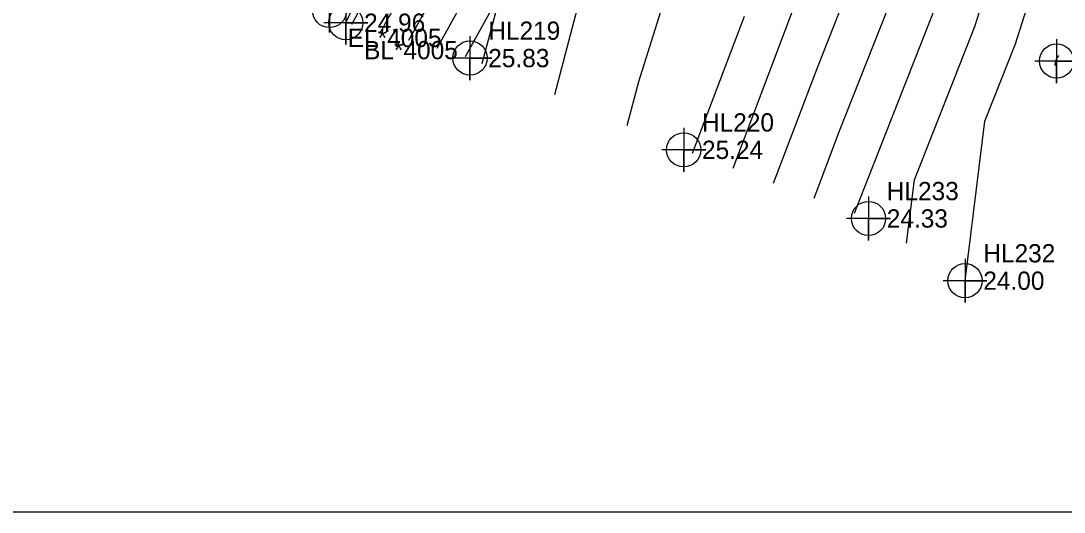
# Model space of a CAD drawing. Extents: x 2531902 to 2533249, y 715219 to 716099.
# Drawn here: x 2532689.5 to 2532832.3, y 715219 to 715286.2 of the extents above; entities that cross this region are included whole.
import ezdxf

# ---------------------------------------------------------------- set-up
doc = ezdxf.new("R2010")
doc.units = 0
for name, color, linetype in [('DTM Contours Major', 7, 'Continuous'), ('DTM Contours Minor', 7, 'Continuous'), ('Exist DTM Breakline', 7, 'Continuous'), ('Exist DTM Breakline Cogo Comment', 7, 'Continuous'), ('Exist DTM Breakline Cogo Elevation', 7, 'Continuous'), ('Exist DTM Breakline Cogo Point CELL', 7, 'Continuous'), ('Exist DTM Regular Point CELL', 7, 'Continuous'), ('Exist DTM Regular Point Cogo Elevation', 7, 'Continuous'), ('Exist DTM Regular Point Cogo Number', 7, 'Continuous'), ('Sheet PDF Layout', 7, 'Continuous')]:
    doc.layers.add(name, color=color, linetype=linetype)

msp = doc.modelspace()

# ---------------------------------------------------------------- linework, layer by layer
at = {"layer": 'DTM Contours Major'}
for points in [[(2532786.98, 715266.08), (2532795.67, 715289.02), (2532797.95, 715294.81), (2532799.31, 715299.08), (2532812.27, 715318.87), (2532813.28, 715320), (2532814.29, 715325.71), (2532815.07, 715330), (2532816.06, 715333.94), (2532816.3, 715340), (2532815.86, 715344.14), (2532816.02, 715350), (2532814.15, 715352.13), (2532811.14, 715357.83)], [(2532818.71, 715250.69), (2532821.42, 715272.52), (2532825.6, 715283.11), (2532830.49, 715298.51), (2532837.64, 715309.36), (2532836.1, 715316.1), (2532837.79, 715320), (2532838.31, 715321.69), (2532839.09, 715330), (2532839.22, 715330.78), (2532840, 715333.2), (2532842.36, 715339.99), (2532842.03, 715345.64)], [(2532751.34, 715319.42), (2532747.87, 715312.77), (2532746.88, 715310.68), (2532735.29, 715286.68), (2532734.78, 715285.75)]]:
    msp.add_lwpolyline(points, dxfattribs=at)
at = {"layer": 'DTM Contours Minor'}
for points in [[(2532762.57, 715276.16), (2532766.2, 715289.92), (2532769.06, 715298.98), (2532779.02, 715321.79), (2532790.29, 715326.86), (2532791.53, 715329.5), (2532792.07, 715330), (2532791.92, 715331.92), (2532790, 715338.05), (2532789.26, 715340), (2532783.35, 715346.65), (2532780.41, 715350), (2532780.15, 715350.2), (2532780, 715350.59), (2532779.74, 715350), (2532775.97, 715344.03), (2532770, 715342.09), (2532769.44, 715340.33), (2532769.23, 715339.92), (2532771.31, 715332.09), (2532768.7, 715327.09), (2532756.94, 715302.15), (2532754.44, 715296.97), (2532746.43, 715282.43)], [(2532810.72, 715255.83), (2532811.8, 715264.47), (2532820.07, 715285.45), (2532827.59, 715309.14), (2532828.61, 715310.7), (2532828.94, 715311.06), (2532830, 715314.11), (2532832.56, 715320)], [(2532772.49, 715271.91), (2532774.08, 715277.94), (2532780.39, 715297.98)], [(2532748.06, 715293.54), (2532742.54, 715283.54)], [(2532792.51, 715264.02), (2532798.61, 715280.1), (2532803.48, 715292.47)], [(2532741.67, 715290.11), (2532738.66, 715284.65)], [(2532752.66, 715280.41), (2532755.28, 715290.33), (2532750.31, 715281.32)], [(2532798.05, 715261.97), (2532801.55, 715271.19), (2532809.01, 715290.13)], [(2532803.59, 715259.91), (2532804.48, 715262.27), (2532814.54, 715287.79)], [(2532781.44, 715268.14), (2532788.55, 715286.89)], [(2532831.51, 715281.51), (2532831.23, 715281.07), (2532831.13, 715280.77), (2532831.05, 715280.57), (2532830.99, 715280.14)]]:
    msp.add_lwpolyline(points, dxfattribs=at)
at = {"layer": 'Exist DTM Breakline'}
msp.add_lwpolyline([(2532733.98, 715285.98), (2532745.96, 715311.46), (2532761.4, 715345.14), (2532779.75, 715380.11), (2532790.74, 715401.87), (2532799.92, 715416.34), (2532808.77, 715435.3)], dxfattribs=at)
at = {"layer": 'Exist DTM Breakline Cogo Point CELL'}
for points in [[(2532731.75, 715290.65), (2532731.75, 715284.65), (2532731.75, 715287.65), (2532734.75, 715287.65), (2532728.75, 715287.65)], [(2532733.98, 715288.98), (2532733.98, 715282.98), (2532733.98, 715285.98), (2532736.98, 715285.98), (2532730.98, 715285.98)]]:
    msp.add_lwpolyline(points, dxfattribs=at)
for centre in [(2532731.75, 715287.65), (2532733.98, 715285.98)]:
    msp.add_circle(centre, 2.34, dxfattribs=at)
at = {"layer": 'Exist DTM Regular Point CELL'}
for points in [[(2532750.97, 715284.14), (2532750.97, 715278.14), (2532750.97, 715281.14), (2532753.97, 715281.14), (2532747.97, 715281.14)], [(2532831.24, 715283.73), (2532831.24, 715277.73), (2532831.24, 715280.73), (2532834.24, 715280.73), (2532828.24, 715280.73)], [(2532780.22, 715271.59), (2532780.22, 715265.59), (2532780.22, 715268.59), (2532783.22, 715268.59), (2532777.22, 715268.59)], [(2532805.5, 715262.2), (2532805.5, 715256.2), (2532805.5, 715259.2), (2532808.5, 715259.2), (2532802.5, 715259.2)], [(2532818.71, 715253.69), (2532818.71, 715247.69), (2532818.71, 715250.69), (2532821.71, 715250.69), (2532815.71, 715250.69)]]:
    msp.add_lwpolyline(points, dxfattribs=at)
for centre in [(2532750.97, 715281.14), (2532831.24, 715280.73), (2532780.22, 715268.59), (2532805.5, 715259.2), (2532818.71, 715250.69)]:
    msp.add_circle(centre, 2.34, dxfattribs=at)
at = {"layer": 'Sheet PDF Layout'}
msp.add_line((2533248.96, 715219.03), (2531901.76, 715219.03), dxfattribs=at)

# ---------------------------------------------------------------- texts
at = {"layer": 'Exist DTM Breakline Cogo Comment'}
for s, p in [('EL*4005', (2532734.25, 715282.65)), ('BL*4005', (2532736.48, 715280.98))]:
    msp.add_text(s, height=2.5, dxfattribs=at).set_placement(p)
at = {"layer": 'Exist DTM Breakline Cogo Elevation'}
msp.add_text('24.96', height=2.5, dxfattribs=at).set_placement((2532736.48, 715284.73))
at = {"layer": 'Exist DTM Regular Point Cogo Elevation'}
for s, p in [('25.83', (2532753.47, 715279.89)), ('25.24', (2532782.72, 715267.34)), ('24.33', (2532808, 715257.95)), ('24.00', (2532821.21, 715249.44))]:
    msp.add_text(s, height=2.5, dxfattribs=at).set_placement(p)
at = {"layer": 'Exist DTM Regular Point Cogo Number'}
for s, p in [('HL219', (2532753.47, 715283.64)), ('HL220', (2532782.72, 715271.09)), ('HL233', (2532808, 715261.7)), ('HL232', (2532821.21, 715253.19))]:
    msp.add_text(s, height=2.5, dxfattribs=at).set_placement(p)

doc.saveas('drawing.dxf')
